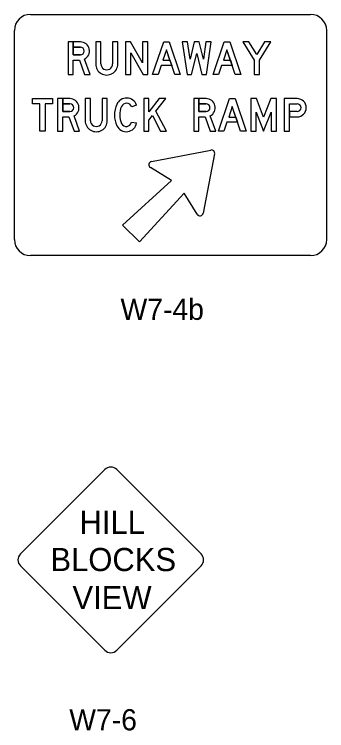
# Model space of a CAD drawing. Extents: x 42133 to 45533, y 41351 to 47951.
# Drawn here: x 44611.2 to 44721.8, y 47475 to 47728.7 of the extents above; entities that cross this region are included whole.
import ezdxf

# ---------------------------------------------------------------- set-up
doc = ezdxf.new("R2010")
doc.units = 0
doc.layers.add('P_TRAF_SIGN_SignDetails', color=7, linetype='Continuous')

msp = doc.modelspace()

# ---------------------------------------------------------------- linework, layer by layer
at = {"layer": 'P_TRAF_SIGN_SignDetails'}
for p, q in [((44616.94, 47728.69), (44716.04, 47728.69)), ((44611.18, 47648.97), (44611.18, 47722.94)), ((44721.76, 47722.94), (44721.76, 47648.97)), ((44639.99, 47718.92), (44639.99, 47711.12)), ((44639.99, 47718.92), (44639.99, 47711.12)), ((44639.99, 47718.92), (44639.99, 47711.12)), ((44636.27, 47698.84), (44636.27, 47691.03)), ((44636.27, 47698.84), (44636.27, 47691.03)), ((44636.27, 47698.84), (44636.27, 47691.03)), ((44654.47, 47696.54), (44652.74, 47695.91)), ((44654.47, 47696.54), (44652.74, 47695.91)), ((44654.47, 47696.54), (44652.74, 47695.91)), ((44708.57, 47697), (44711.33, 47697)), ((44708.57, 47697), (44711.33, 47697)), ((44708.57, 47692.39), (44711.33, 47692.39)), ((44652.65, 47690.53), (44654.47, 47690.26)), ((44652.65, 47690.53), (44654.47, 47690.26)), ((44652.65, 47690.53), (44654.47, 47690.26)), ((44716.04, 47643.22), (44616.94, 47643.22)), ((44613.35, 47537.6), (44643.2, 47567.45)), ((44647.47, 47567.45), (44677.31, 47537.6)), ((44643.2, 47503.48), (44613.35, 47533.33)), ((44677.31, 47533.33), (44647.47, 47503.48))]:
    msp.add_line(p, q, dxfattribs=at)
for points in [[(44634.57, 47714.32), (44632.04, 47714.32), (44632.04, 47718.92), (44630.2, 47718.92), (44630.2, 47707.4), (44632.04, 47707.4), (44632.04, 47712.47), (44634.21, 47712.47), (44636.07, 47707.4), (44638.03, 47707.4), (44636.04, 47712.82)], [(44634.57, 47714.32), (44632.04, 47714.32), (44632.04, 47718.92), (44630.2, 47718.92), (44630.2, 47707.4), (44632.04, 47707.4), (44632.04, 47712.47), (44634.21, 47712.47), (44636.07, 47707.4), (44638.03, 47707.4), (44636.04, 47712.82)], [(44634.57, 47718.92), (44630.2, 47718.92), (44630.2, 47707.4), (44632.04, 47707.4), (44632.04, 47712.47), (44634.21, 47712.47), (44636.07, 47707.4), (44638.03, 47707.4), (44636.04, 47712.82)], [(44632.04, 47718.92), (44632.04, 47717.08), (44634.57, 47717.08)], [(44634.57, 47718.92), (44632.04, 47718.92)], [(44632.04, 47718.92), (44632.04, 47717.08), (44634.57, 47717.08)], [(44634.57, 47718.92), (44632.04, 47718.92)], [(44641.83, 47711.12), (44641.83, 47718.92), (44639.99, 47718.92)], [(44641.83, 47711.12), (44641.83, 47718.92), (44639.99, 47718.92)], [(44641.83, 47711.12), (44641.83, 47718.92), (44639.99, 47718.92)], [(44647.82, 47711.12), (44647.82, 47718.92), (44645.98, 47718.92), (44645.98, 47711.12)], [(44647.82, 47711.12), (44647.82, 47718.92), (44645.98, 47718.92), (44645.98, 47711.12)], [(44647.82, 47711.12), (44647.82, 47718.92), (44645.98, 47718.92), (44645.98, 47711.12)], [(44634.57, 47717.08), (44632.04, 47717.08), (44632.04, 47714.32), (44634.57, 47714.32)], [(44630.85, 47694.23), (44628.32, 47694.23), (44628.32, 47698.84), (44626.48, 47698.84), (44626.48, 47687.32), (44628.32, 47687.32), (44628.32, 47692.39), (44630.49, 47692.39), (44632.35, 47687.32), (44634.31, 47687.32), (44632.32, 47692.74)], [(44630.85, 47694.23), (44628.32, 47694.23), (44628.32, 47698.84), (44626.48, 47698.84), (44626.48, 47687.32), (44628.32, 47687.32), (44628.32, 47692.39), (44630.49, 47692.39), (44632.35, 47687.32), (44634.31, 47687.32), (44632.32, 47692.74)], [(44630.85, 47698.84), (44626.48, 47698.84), (44626.48, 47687.32), (44628.32, 47687.32), (44628.32, 47692.39), (44630.49, 47692.39), (44632.35, 47687.32), (44634.31, 47687.32), (44632.32, 47692.74)], [(44628.32, 47698.84), (44628.32, 47697), (44630.85, 47697)], [(44630.85, 47698.84), (44628.32, 47698.84)], [(44628.32, 47698.84), (44628.32, 47697), (44630.85, 47697)], [(44630.85, 47698.84), (44628.32, 47698.84)], [(44638.11, 47691.03), (44638.11, 47698.84), (44636.27, 47698.84)], [(44638.11, 47691.03), (44638.11, 47698.84), (44636.27, 47698.84)], [(44638.11, 47691.03), (44638.11, 47698.84), (44636.27, 47698.84)], [(44644.1, 47691.03), (44644.1, 47698.84), (44642.26, 47698.84), (44642.26, 47691.03)], [(44644.1, 47691.03), (44644.1, 47698.84), (44642.26, 47698.84), (44642.26, 47691.03)], [(44644.1, 47691.03), (44644.1, 47698.84), (44642.26, 47698.84), (44642.26, 47691.03)], [(44679.08, 47694.23), (44676.54, 47694.23), (44676.54, 47698.84), (44674.7, 47698.84), (44674.7, 47687.32), (44676.54, 47687.32), (44676.54, 47692.39), (44678.71, 47692.39), (44680.57, 47687.32), (44682.53, 47687.32), (44680.54, 47692.74)], [(44679.08, 47694.23), (44676.54, 47694.23), (44676.54, 47698.84), (44674.7, 47698.84), (44674.7, 47687.32), (44676.54, 47687.32), (44676.54, 47692.39), (44678.71, 47692.39), (44680.57, 47687.32), (44682.53, 47687.32), (44680.54, 47692.74)], [(44679.08, 47698.84), (44674.7, 47698.84), (44674.7, 47687.32), (44676.54, 47687.32), (44676.54, 47692.39), (44678.71, 47692.39), (44680.57, 47687.32), (44682.53, 47687.32), (44680.54, 47692.74)], [(44676.54, 47698.84), (44676.54, 47697), (44679.08, 47697)], [(44679.08, 47698.84), (44676.54, 47698.84)], [(44676.54, 47698.84), (44676.54, 47697), (44679.08, 47697)], [(44679.08, 47698.84), (44676.54, 47698.84)], [(44711.33, 47698.84), (44706.73, 47698.84), (44706.73, 47687.32), (44708.57, 47687.32), (44708.57, 47692.39)], [(44711.33, 47698.84), (44706.73, 47698.84), (44706.73, 47687.32), (44708.57, 47687.32), (44708.57, 47697)], [(44711.33, 47698.84), (44706.73, 47698.84), (44706.73, 47687.32), (44708.57, 47687.32), (44708.57, 47697)], [(44630.85, 47697), (44628.32, 47697), (44628.32, 47694.23), (44630.85, 47694.23)], [(44679.08, 47697), (44676.54, 47697), (44676.54, 47694.23), (44679.08, 47694.23)], [(44711.33, 47694.23), (44708.57, 47694.23), (44708.57, 47697), (44711.33, 47697)], [(44711.33, 47694.23), (44708.57, 47694.23), (44708.57, 47692.39), (44711.33, 47692.39)], [(44711.33, 47694.23), (44708.57, 47694.23), (44708.57, 47692.39), (44711.33, 47692.39)], [(44659.74, 47676.57), (44680.72, 47680.64)], [(44659.74, 47676.57), (44680.72, 47680.64)], [(44659.74, 47676.57), (44680.72, 47680.64)], [(44682.11, 47679.25), (44678.04, 47658.27)], [(44682.11, 47679.25), (44678.04, 47658.27)], [(44682.11, 47679.25), (44678.04, 47658.27)], [(44675.87, 47657.88), (44671.3, 47665.33), (44655.49, 47648.07), (44649.54, 47654.02), (44666.81, 47669.83), (44659.35, 47674.4)], [(44675.87, 47657.88), (44671.3, 47665.33), (44655.49, 47648.07), (44649.54, 47654.02), (44666.81, 47669.83), (44659.35, 47674.4)], [(44675.87, 47657.88), (44671.3, 47665.33), (44655.49, 47648.07), (44649.54, 47654.02), (44666.81, 47669.83), (44659.35, 47674.4)]]:
    msp.add_lwpolyline(points, dxfattribs=at)
for points in [[(44658.42, 47707.4), (44658.42, 47718.92), (44656.58, 47718.92), (44656.58, 47711.52), (44652.35, 47718.92), (44650.59, 47718.92), (44650.59, 47707.4), (44652.43, 47707.4), (44652.43, 47715.06), (44656.81, 47707.4)], [(44658.42, 47707.4), (44658.42, 47718.92), (44656.58, 47718.92), (44656.58, 47711.52), (44652.35, 47718.92), (44650.59, 47718.92), (44650.59, 47707.4), (44652.43, 47707.4), (44652.43, 47715.06), (44656.81, 47707.4)], [(44658.42, 47707.4), (44658.42, 47718.92), (44656.58, 47718.92), (44656.58, 47711.52), (44652.35, 47718.92), (44650.59, 47718.92), (44650.59, 47707.4), (44652.43, 47707.4), (44652.43, 47715.06), (44656.81, 47707.4)], [(44663.17, 47710.57), (44662.1, 47707.4), (44660.15, 47707.4), (44664.07, 47718.92), (44666.03, 47718.92), (44669.94, 47707.4), (44668, 47707.4), (44666.92, 47710.57)], [(44660.15, 47707.4), (44664.07, 47718.92), (44666.03, 47718.92), (44669.94, 47707.4), (44668, 47707.4), (44665.05, 47716.08), (44663.8, 47712.41), (44666.29, 47712.41), (44666.92, 47710.57), (44663.17, 47710.57), (44662.1, 47707.4)], [(44660.15, 47707.4), (44664.07, 47718.92), (44666.03, 47718.92), (44669.94, 47707.4), (44668, 47707.4), (44665.05, 47716.08), (44663.8, 47712.41), (44666.29, 47712.41), (44666.92, 47710.57), (44663.17, 47710.57), (44662.1, 47707.4)], [(44673.95, 47707.4), (44675.76, 47714.78), (44677.57, 47707.4), (44679.19, 47707.4), (44680.89, 47718.92), (44679.02, 47718.92), (44678.13, 47712.86), (44676.64, 47718.92), (44674.88, 47718.92), (44673.39, 47712.86), (44672.5, 47718.92), (44670.63, 47718.92), (44672.33, 47707.4)], [(44673.95, 47707.4), (44675.76, 47714.78), (44677.57, 47707.4), (44679.19, 47707.4), (44680.89, 47718.92), (44679.02, 47718.92), (44678.13, 47712.86), (44676.64, 47718.92), (44674.88, 47718.92), (44673.39, 47712.86), (44672.5, 47718.92), (44670.63, 47718.92), (44672.33, 47707.4)], [(44673.95, 47707.4), (44675.76, 47714.78), (44677.57, 47707.4), (44679.19, 47707.4), (44680.89, 47718.92), (44679.02, 47718.92), (44678.13, 47712.86), (44676.64, 47718.92), (44674.88, 47718.92), (44673.39, 47712.86), (44672.5, 47718.92), (44670.63, 47718.92), (44672.33, 47707.4)], [(44684.6, 47710.57), (44683.52, 47707.4), (44681.58, 47707.4), (44685.49, 47718.92), (44687.45, 47718.92), (44691.37, 47707.4), (44689.42, 47707.4), (44688.35, 47710.57)], [(44681.58, 47707.4), (44685.49, 47718.92), (44687.45, 47718.92), (44691.37, 47707.4), (44689.42, 47707.4), (44686.47, 47716.08), (44685.23, 47712.41), (44687.72, 47712.41), (44688.35, 47710.57), (44684.6, 47710.57), (44683.52, 47707.4)], [(44681.58, 47707.4), (44685.49, 47718.92), (44687.45, 47718.92), (44691.37, 47707.4), (44689.42, 47707.4), (44686.47, 47716.08), (44685.23, 47712.41), (44687.72, 47712.41), (44688.35, 47710.57), (44684.6, 47710.57), (44683.52, 47707.4)], [(44696.09, 47707.4), (44697.94, 47707.4), (44697.94, 47712.47), (44701.97, 47718.92), (44699.79, 47718.92), (44697.01, 47714.47), (44694.23, 47718.92), (44692.06, 47718.92), (44696.09, 47712.47)], [(44696.09, 47707.4), (44697.94, 47707.4), (44697.94, 47712.47), (44701.97, 47718.92), (44699.79, 47718.92), (44697.01, 47714.47), (44694.23, 47718.92), (44692.06, 47718.92), (44696.09, 47712.47)], [(44696.09, 47707.4), (44697.94, 47707.4), (44697.94, 47712.47), (44701.97, 47718.92), (44699.79, 47718.92), (44697.01, 47714.47), (44694.23, 47718.92), (44692.06, 47718.92), (44696.09, 47712.47)], [(44663.8, 47712.41), (44666.29, 47712.41), (44665.05, 47716.08)], [(44685.23, 47712.41), (44687.72, 47712.41), (44686.47, 47716.08)], [(44624.75, 47698.84), (44624.75, 47697), (44622.1, 47697), (44622.1, 47687.32), (44620.26, 47687.32), (44620.26, 47697), (44617.61, 47697), (44617.61, 47698.84)], [(44624.75, 47698.84), (44624.75, 47697), (44622.1, 47697), (44622.1, 47687.32), (44620.26, 47687.32), (44620.26, 47697), (44617.61, 47697), (44617.61, 47698.84)], [(44624.75, 47698.84), (44624.75, 47697), (44622.1, 47697), (44622.1, 47687.32), (44620.26, 47687.32), (44620.26, 47697), (44617.61, 47697), (44617.61, 47698.84)], [(44658.85, 47687.32), (44658.85, 47691.22), (44660.1, 47692.81), (44662.99, 47687.32), (44665.07, 47687.32), (44661.34, 47694.4), (44664.83, 47698.84), (44662.49, 47698.84), (44658.85, 47694.21), (44658.85, 47698.84), (44657.01, 47698.84), (44657.01, 47687.32)], [(44658.85, 47687.32), (44658.85, 47691.22), (44660.1, 47692.81), (44662.99, 47687.32), (44665.07, 47687.32), (44661.34, 47694.4), (44664.83, 47698.84), (44662.49, 47698.84), (44658.85, 47694.21), (44658.85, 47698.84), (44657.01, 47698.84), (44657.01, 47687.32)], [(44658.85, 47687.32), (44658.85, 47691.22), (44660.1, 47692.81), (44662.99, 47687.32), (44665.07, 47687.32), (44661.34, 47694.4), (44664.83, 47698.84), (44662.49, 47698.84), (44658.85, 47694.21), (44658.85, 47698.84), (44657.01, 47698.84), (44657.01, 47687.32)], [(44686.48, 47690.49), (44685.4, 47687.32), (44683.46, 47687.32), (44687.37, 47698.84), (44689.33, 47698.84), (44693.25, 47687.32), (44691.3, 47687.32), (44690.22, 47690.49)], [(44683.46, 47687.32), (44687.37, 47698.84), (44689.33, 47698.84), (44693.25, 47687.32), (44691.3, 47687.32), (44688.35, 47695.99), (44687.11, 47692.33), (44689.6, 47692.33), (44690.22, 47690.49), (44686.48, 47690.49), (44685.4, 47687.32)], [(44683.46, 47687.32), (44687.37, 47698.84), (44689.33, 47698.84), (44693.25, 47687.32), (44691.3, 47687.32), (44688.35, 47695.99), (44687.11, 47692.33), (44689.6, 47692.33), (44690.22, 47690.49), (44686.48, 47690.49), (44685.4, 47687.32)], [(44703.96, 47687.32), (44703.96, 47698.84), (44702.05, 47698.84), (44699.47, 47692.32), (44696.88, 47698.84), (44694.98, 47698.84), (44694.98, 47687.32), (44696.82, 47687.32), (44696.82, 47694), (44699.47, 47687.32), (44702.12, 47694), (44702.12, 47687.32)], [(44703.96, 47687.32), (44703.96, 47698.84), (44702.05, 47698.84), (44699.47, 47692.32), (44696.88, 47698.84), (44694.98, 47698.84), (44694.98, 47687.32), (44696.82, 47687.32), (44696.82, 47694), (44699.47, 47687.32), (44702.12, 47694), (44702.12, 47687.32)], [(44703.96, 47687.32), (44703.96, 47698.84), (44702.05, 47698.84), (44699.47, 47692.32), (44696.88, 47698.84), (44694.98, 47698.84), (44694.98, 47687.32), (44696.82, 47687.32), (44696.82, 47694), (44699.47, 47687.32), (44702.12, 47694), (44702.12, 47687.32)], [(44687.11, 47692.33), (44689.6, 47692.33), (44688.35, 47695.99)]]:
    msp.add_lwpolyline(points, close=True, dxfattribs=at)
for centre, radius, start, end in [((44616.94, 47722.94), 5.75, 90, 180), ((44716.04, 47722.94), 5.75, 360, 90), ((44680.95, 47679.47), 1.18, 349.0223, 100.9777), ((44680.95, 47679.47), 1.18, 349.0223, 100.9777), ((44680.95, 47679.47), 1.18, 349.0223, 100.9777), ((44659.97, 47675.4), 1.18, 100.9777, 238.5155), ((44659.97, 47675.4), 1.18, 100.9777, 238.5155), ((44659.97, 47675.4), 1.18, 100.9777, 238.5155), ((44676.88, 47658.49), 1.18, 211.4845, 349.0223), ((44676.88, 47658.49), 1.18, 211.4845, 349.0223), ((44676.88, 47658.49), 1.18, 211.4845, 349.0223), ((44616.94, 47648.97), 5.75, 180, 270), ((44716.04, 47648.97), 5.75, 270, 360), ((44645.34, 47565.3), 3.02, 45, 135), ((44615.49, 47535.46), 3.02, 135, 224.9964), ((44675.18, 47535.46), 3.02, 315.0024, 45), ((44645.33, 47505.61), 3.02, 224.9955, 315.0023)]:
    msp.add_arc(centre, radius, start, end, dxfattribs=at)
for centre, major_axis, ratio, start_param, end_param in [((44634.57, 47715.7), (0, 3.23), 0.999993, 3.613317, 6.283185), ((44634.57, 47715.7), (0, 3.23), 0.999993, 3.613317, 6.283185), ((44634.57, 47715.7), (0, 3.23), 0.999993, 3.613317, 6.283185), ((44634.57, 47715.7), (0, 1.38), 0.999993, 3.141593, 6.283185), ((44634.57, 47715.7), (0, 1.38), 0.999993, 3.141593, 6.283185), ((44634.57, 47715.7), (0, 1.38), 0.999993, 3.141593, 6.283185), ((44643.91, 47711.12), (0, 3.92), 0.999994, 1.570796, 4.712389), ((44643.91, 47711.12), (0, 3.92), 0.999994, 1.570796, 4.712389), ((44643.91, 47711.12), (0, 3.92), 0.999994, 1.570796, 4.712389), ((44643.91, 47711.12), (0, 2.07), 0.999994, 1.570796, 4.712389), ((44643.91, 47711.12), (0, 2.07), 0.999994, 1.570796, 4.712389), ((44643.91, 47711.12), (0, 2.07), 0.999994, 1.570796, 4.712389), ((44630.85, 47695.61), (0, 3.23), 0.999997, 3.613317, 6.283185), ((44630.85, 47695.61), (0, 3.23), 0.999997, 3.613317, 6.283185), ((44630.85, 47695.61), (0, 3.23), 0.999997, 3.613317, 6.283185), ((44650.9, 47695.24), (0, 3.8), 0.999997, 5.061866, 7.434148), ((44650.9, 47695.24), (0, 3.8), 0.999997, 5.061866, 7.434148), ((44650.9, 47695.24), (0, 3.8), 0.999997, 5.061866, 7.434148), ((44679.08, 47695.61), (0, 3.23), 0.999997, 3.613317, 6.283185), ((44679.08, 47695.61), (0, 3.23), 0.999997, 3.613317, 6.283185), ((44679.08, 47695.61), (0, 3.23), 0.999997, 3.613317, 6.283185), ((44711.33, 47695.61), (0, 3.23), 0.999997, 3.141593, 6.283185), ((44711.33, 47695.61), (0, 3.23), 0.999997, 3.141593, 6.283185), ((44711.33, 47695.61), (0, 3.23), 0.999997, 3.141593, 6.283185), ((44630.85, 47695.61), (0, 1.38), 0.999997, 3.141593, 6.283185), ((44630.85, 47695.61), (0, 1.38), 0.999997, 3.141593, 6.283185), ((44630.85, 47695.61), (0, 1.38), 0.999997, 3.141593, 6.283185), ((44655.74, 47693.08), (0, 9.1), 0.999997, 1.150963, 2.004476), ((44655.74, 47693.08), (0, 9.1), 0.999997, 1.150963, 2.004476), ((44655.74, 47693.08), (0, 9.1), 0.999997, 1.150963, 2.004476), ((44655.74, 47693.08), (0, 7.26), 0.999997, 1.150963, 2.004476), ((44655.74, 47693.08), (0, 7.26), 0.999997, 1.150963, 2.004476), ((44655.74, 47693.08), (0, 7.26), 0.999997, 1.150963, 2.004476), ((44650.9, 47695.24), (0, 1.96), 0.999997, 5.061866, 7.434148), ((44650.9, 47695.24), (0, 1.96), 0.999997, 5.061866, 7.434148), ((44650.9, 47695.24), (0, 1.96), 0.999997, 5.061866, 7.434148), ((44679.08, 47695.61), (0, 1.38), 0.999997, 3.141593, 6.283185), ((44679.08, 47695.61), (0, 1.38), 0.999997, 3.141593, 6.283185), ((44679.08, 47695.61), (0, 1.38), 0.999997, 3.141593, 6.283185), ((44711.33, 47695.61), (0, 1.38), 0.999997, 3.141593, 6.283185), ((44711.33, 47695.61), (0, 1.38), 0.999997, 3.141593, 6.283185), ((44711.33, 47695.61), (0, 1.38), 0.999997, 3.141593, 6.283185), ((44640.19, 47691.03), (0, 3.92), 0.999999, 1.570796, 4.712389), ((44640.19, 47691.03), (0, 3.92), 0.999999, 1.570796, 4.712389), ((44640.19, 47691.03), (0, 3.92), 0.999999, 1.570796, 4.712389), ((44640.19, 47691.03), (0, 2.07), 0.999999, 1.570796, 4.712389), ((44640.19, 47691.03), (0, 2.07), 0.999999, 1.570796, 4.712389), ((44640.19, 47691.03), (0, 2.07), 0.999999, 1.570796, 4.712389), ((44650.83, 47690.8), (0, 3.69), 0.999997, 2.004476, 4.564141), ((44650.83, 47690.8), (0, 3.69), 0.999997, 2.004476, 4.564141), ((44650.83, 47690.8), (0, 3.69), 0.999997, 2.004476, 4.564141), ((44650.83, 47690.8), (0, 1.84), 0.999997, 2.004476, 4.564141), ((44650.83, 47690.8), (0, 1.84), 0.999997, 2.004476, 4.564141), ((44650.83, 47690.8), (0, 1.84), 0.999997, 2.004476, 4.564141)]:
    msp.add_ellipse(centre, major_axis=major_axis, ratio=ratio, start_param=start_param, end_param=end_param, dxfattribs=at)

# ---------------------------------------------------------------- texts
for s, height, p in [('W7-4b', 7.5, (44648.78, 47620.47)), ('HILL', 8.203, (44634.25, 47544.65)), ('BLOCKS', 8.203, (44623.96, 47531.5)), ('VIEW', 8.203, (44631.76, 47518.02)), ('W7-6', 7.5, (44630.63, 47475.09))]:
    msp.add_text(s, height=height, dxfattribs=at).set_placement(p)

doc.saveas('drawing.dxf')
